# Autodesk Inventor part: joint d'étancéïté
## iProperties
Shininess: 64.0
Length Units: 11269
Angle Units: 11279
Time Units: 11290
Mass Units: 11283
Length Display Precision: 3
Angle Display Precision: 2
Compacted: True
Part Number: joint d'étancéïté
Document SubType Name: Modeling
Created: 2005-01
Material: Par défaut
Designer: Flavien MARTY
Density: 0.0
Volumn: 0.0
Area: 0.0
PropertySet Name: Model Information
Control State: 0
Master: False
Checked Out: False
Author: Flavien MARTY
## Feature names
1. Révolution1 [Revolution]
